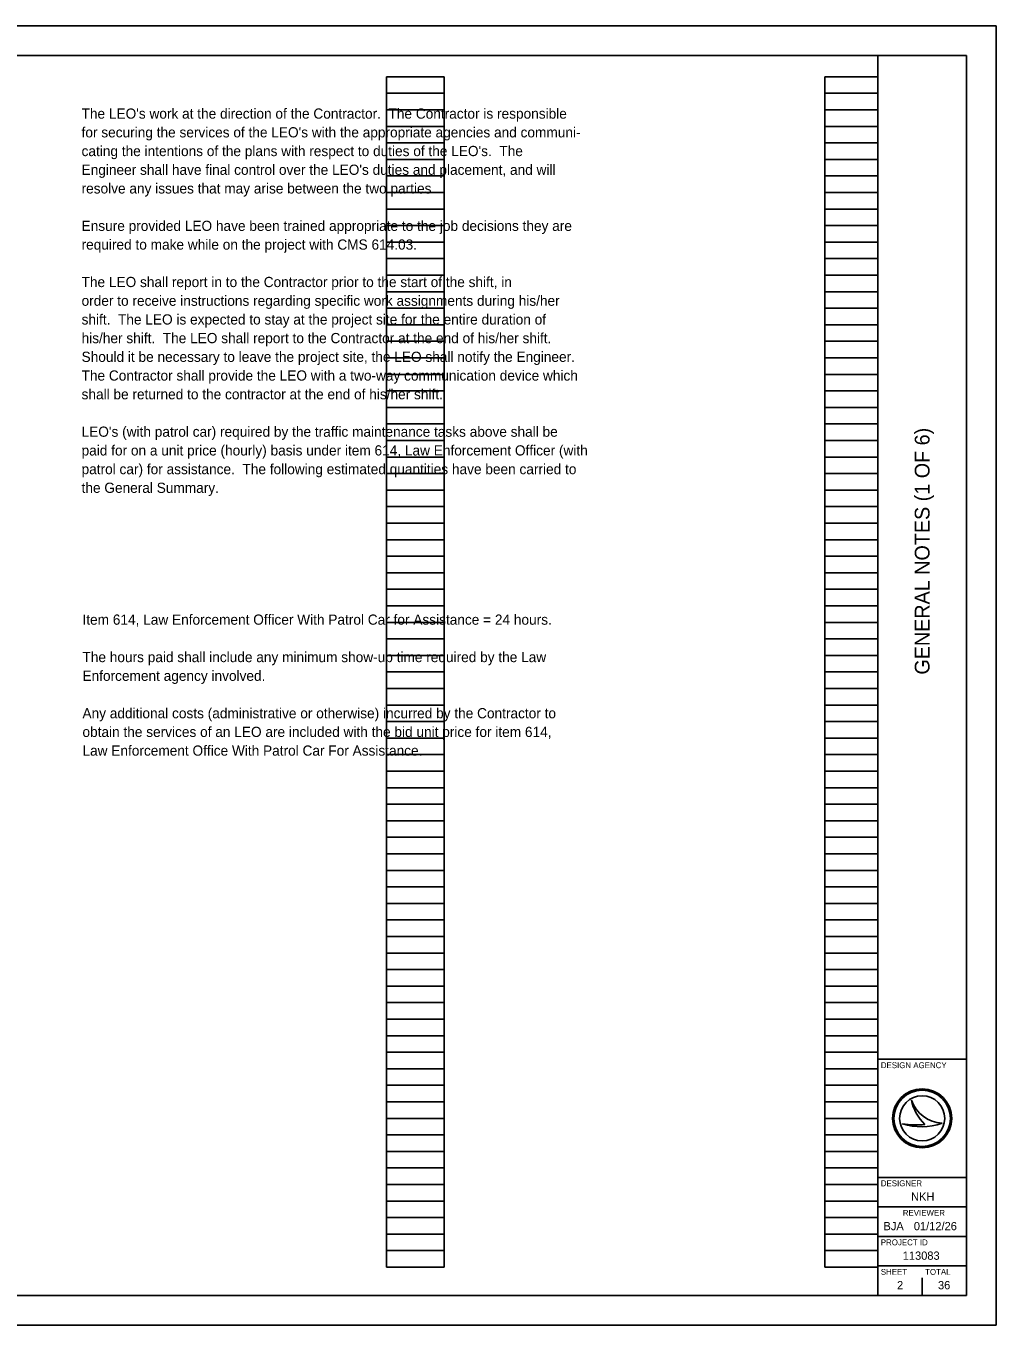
# Model space of a CAD drawing. Extents: x 0 to 34, y 0 to 22.
# Drawn here: x 17.58 to 34, y 0 to 22 of the extents above; entities that cross this region are included whole.
import ezdxf

# ---------------------------------------------------------------- set-up
doc = ezdxf.new("R2010")
doc.units = 0
for name, color, linetype in [('SH_Border', 7, 'Continuous'), ('SH_Cut_Line', 7, 'Continuous'), ('SH_Data', 7, 'Continuous'), ('SH_Text', 7, 'Continuous')]:
    doc.layers.add(name, color=color, linetype=linetype)

msp = doc.modelspace()

# ---------------------------------------------------------------- linework, layer by layer
at = {"layer": 'SH_Border'}
for p, q in [((32, 0.5), (32, 21.5)), ((32, 4.5), (33.5, 4.5)), ((32, 2.5), (33.5, 2.5)), ((32, 2), (33.5, 2)), ((32, 1.5), (33.5, 1.5)), ((32, 1), (33.5, 1))]:
    msp.add_line(p, q, dxfattribs=at)
msp.add_lwpolyline([(1.5, 21.5), (33.5, 21.5), (33.5, 0.5), (1.5, 0.5)], close=True, dxfattribs=at)
at = {"layer": 'SH_Cut_Line'}
msp.add_lwpolyline([(0, 0), (34, 0), (34, 22), (0, 22)], close=True, dxfattribs=at)
at = {"layer": 'SH_Data'}
for p, q in [((23.68, 0.98), (23.68, 21.14)), ((23.68, 21.14), (24.66, 21.14)), ((24.66, 0.98), (24.66, 21.14)), ((31.1, 0.98), (31.1, 21.14)), ((31.1, 21.14), (32, 21.14)), ((32, 0.98), (32, 21.14)), ((23.68, 20.86), (24.66, 20.86)), ((31.1, 20.86), (32, 20.86)), ((23.68, 20.58), (24.66, 20.58)), ((31.1, 20.58), (32, 20.58)), ((23.68, 20.3), (24.66, 20.3)), ((31.1, 20.3), (32, 20.3)), ((23.68, 20.02), (24.66, 20.02)), ((31.1, 20.02), (32, 20.02)), ((23.68, 19.74), (24.66, 19.74)), ((31.1, 19.74), (32, 19.74)), ((23.68, 19.46), (24.66, 19.46)), ((31.1, 19.46), (32, 19.46)), ((23.68, 19.18), (24.66, 19.18)), ((31.1, 19.18), (32, 19.18)), ((23.68, 18.9), (24.66, 18.9)), ((31.1, 18.9), (32, 18.9)), ((23.68, 18.62), (24.66, 18.62)), ((31.1, 18.62), (32, 18.62)), ((23.68, 18.34), (24.66, 18.34)), ((31.1, 18.34), (32, 18.34)), ((23.68, 18.06), (24.66, 18.06)), ((31.1, 18.06), (32, 18.06)), ((23.68, 17.78), (24.66, 17.78)), ((31.1, 17.78), (32, 17.78)), ((23.68, 17.5), (24.66, 17.5)), ((31.1, 17.5), (32, 17.5)), ((23.68, 17.22), (24.66, 17.22)), ((31.1, 17.22), (32, 17.22)), ((23.68, 16.94), (24.66, 16.94)), ((31.1, 16.94), (32, 16.94)), ((23.68, 16.66), (24.66, 16.66)), ((31.1, 16.66), (32, 16.66)), ((23.68, 16.38), (24.66, 16.38)), ((31.1, 16.38), (32, 16.38)), ((23.68, 16.1), (24.66, 16.1)), ((31.1, 16.1), (32, 16.1)), ((23.68, 15.82), (24.66, 15.82)), ((31.1, 15.82), (32, 15.82)), ((23.68, 15.54), (24.66, 15.54)), ((31.1, 15.54), (32, 15.54)), ((23.68, 15.26), (24.66, 15.26)), ((31.1, 15.26), (32, 15.26)), ((23.68, 14.98), (24.66, 14.98)), ((31.1, 14.98), (32, 14.98)), ((23.68, 14.7), (24.66, 14.7)), ((31.1, 14.7), (32, 14.7)), ((23.68, 14.42), (24.66, 14.42)), ((31.1, 14.42), (32, 14.42)), ((23.68, 14.14), (24.66, 14.14)), ((31.1, 14.14), (32, 14.14)), ((23.68, 13.86), (24.66, 13.86)), ((31.1, 13.86), (32, 13.86)), ((23.68, 13.58), (24.66, 13.58)), ((31.1, 13.58), (32, 13.58)), ((23.68, 13.3), (24.66, 13.3)), ((31.1, 13.3), (32, 13.3)), ((23.68, 13.02), (24.66, 13.02)), ((31.1, 13.02), (32, 13.02)), ((23.68, 12.74), (24.66, 12.74)), ((31.1, 12.74), (32, 12.74)), ((23.68, 12.46), (24.66, 12.46)), ((31.1, 12.46), (32, 12.46)), ((23.68, 12.18), (24.66, 12.18)), ((31.1, 12.18), (32, 12.18)), ((23.68, 11.9), (24.66, 11.9)), ((31.1, 11.9), (32, 11.9)), ((23.68, 11.62), (24.66, 11.62)), ((31.1, 11.62), (32, 11.62)), ((23.68, 11.34), (24.66, 11.34)), ((31.1, 11.34), (32, 11.34)), ((23.68, 11.06), (24.66, 11.06)), ((31.1, 11.06), (32, 11.06)), ((23.68, 10.78), (24.66, 10.78)), ((31.1, 10.78), (32, 10.78)), ((23.68, 10.5), (24.66, 10.5)), ((31.1, 10.5), (32, 10.5)), ((23.68, 10.22), (24.66, 10.22)), ((31.1, 10.22), (32, 10.22)), ((23.68, 9.94), (24.66, 9.94)), ((31.1, 9.94), (32, 9.94)), ((23.68, 9.66), (24.66, 9.66)), ((31.1, 9.66), (32, 9.66)), ((23.68, 9.38), (24.66, 9.38)), ((31.1, 9.38), (32, 9.38)), ((23.68, 9.1), (24.66, 9.1)), ((31.1, 9.1), (32, 9.1)), ((23.68, 8.82), (24.66, 8.82)), ((31.1, 8.82), (32, 8.82)), ((23.68, 8.54), (24.66, 8.54)), ((31.1, 8.54), (32, 8.54)), ((23.68, 8.26), (24.66, 8.26)), ((31.1, 8.26), (32, 8.26)), ((23.68, 7.98), (24.66, 7.98)), ((31.1, 7.98), (32, 7.98)), ((23.68, 7.7), (24.66, 7.7)), ((31.1, 7.7), (32, 7.7)), ((23.68, 7.42), (24.66, 7.42)), ((31.1, 7.42), (32, 7.42)), ((23.68, 7.14), (24.66, 7.14)), ((31.1, 7.14), (32, 7.14)), ((23.68, 6.86), (24.66, 6.86)), ((31.1, 6.86), (32, 6.86)), ((23.68, 6.58), (24.66, 6.58)), ((31.1, 6.58), (32, 6.58)), ((23.68, 6.3), (24.66, 6.3)), ((31.1, 6.3), (32, 6.3)), ((23.68, 6.02), (24.66, 6.02)), ((31.1, 6.02), (32, 6.02)), ((23.68, 5.74), (24.66, 5.74)), ((31.1, 5.74), (32, 5.74)), ((23.68, 5.46), (24.66, 5.46)), ((31.1, 5.46), (32, 5.46)), ((23.68, 5.18), (24.66, 5.18)), ((31.1, 5.18), (32, 5.18)), ((23.68, 4.9), (24.66, 4.9)), ((31.1, 4.9), (32, 4.9)), ((23.68, 4.62), (24.66, 4.62)), ((31.1, 4.62), (32, 4.62)), ((23.68, 4.34), (24.66, 4.34)), ((31.1, 4.34), (32, 4.34)), ((23.68, 4.06), (24.66, 4.06)), ((31.1, 4.06), (32, 4.06)), ((23.68, 3.78), (24.66, 3.78)), ((31.1, 3.78), (32, 3.78)), ((32.567, 3.81), (32.567, 3.81)), ((23.68, 3.5), (24.66, 3.5)), ((31.1, 3.5), (32, 3.5)), ((32.417, 3.41), (32.417, 3.41)), ((32.75, 3.5), (32.75, 3.5)), ((33.087, 3.419), (33.087, 3.419)), ((23.68, 3.22), (24.66, 3.22)), ((31.1, 3.22), (32, 3.22)), ((23.68, 2.94), (24.66, 2.94)), ((31.1, 2.94), (32, 2.94)), ((23.68, 2.66), (24.66, 2.66)), ((31.1, 2.66), (32, 2.66)), ((23.68, 2.38), (24.66, 2.38)), ((31.1, 2.38), (32, 2.38)), ((23.68, 2.1), (24.66, 2.1)), ((31.1, 2.1), (32, 2.1)), ((23.68, 1.82), (24.66, 1.82)), ((31.1, 1.82), (32, 1.82)), ((23.68, 1.54), (24.66, 1.54)), ((31.1, 1.54), (32, 1.54)), ((23.68, 1.26), (24.66, 1.26)), ((31.1, 1.26), (32, 1.26)), ((23.68, 0.98), (24.66, 0.98)), ((31.1, 0.98), (32, 0.98)), ((32.375, 0.675), (32.375, 0.675)), ((32.75, 0.5), (32.75, 0.8))]:
    msp.add_line(p, q, dxfattribs=at)
for radius in [0.5, 0.477, 0.477, 0.382]:
    msp.add_circle((32.75, 3.5), radius, dxfattribs=at)
for centre, radius, start, end in [((33.116, 3.998), 0.58, 198.9257, 198.9319), ((33.347, 3.97), 0.796, 191.6379, 191.6421), ((33.116, 3.998), 0.58, 198.9319, 267.1657), ((33.347, 3.97), 0.796, 191.6421, 226.0947), ((32.739, 4.37), 1.013, 251.4576, 290.0832), ((32.648, 4.654), 1.266, 259.4964, 259.4995), ((32.739, 4.37), 1.013, 251.4527, 251.4576), ((32.648, 4.654), 1.266, 259.4995, 276.6672)]:
    msp.add_arc(centre, radius, start, end, dxfattribs=at)

# ---------------------------------------------------------------- texts
msp.add_text('GENERAL NOTES (1 OF 6)', height=0.25, rotation=90, dxfattribs=at).set_placement((32.875, 11.015))
for s, height, p in [('DESIGN AGENCY', 0.1, (32.05, 4.35)), ('DESIGNER', 0.1, (32.05, 2.35)), ('NKH', 0.14, (32.562, 2.105)), ('REVIEWER', 0.1, (32.422, 1.85)), ('BJA', 0.14, (32.095, 1.605)), ('01/12/26', 0.14, (32.609, 1.605)), ('PROJECT ID', 0.1, (32.05, 1.35)), ('113083', 0.14, (32.421, 1.105)), ('SHEET', 0.1, (32.05, 0.85)), ('TOTAL', 0.1, (32.8, 0.85)), ('2', 0.14, (32.325, 0.605)), ('36', 0.14, (33.018, 0.605))]:
    msp.add_text(s, height=height, dxfattribs=at).set_placement(p)
at = {"layer": 'SH_Text'}
for s, p in [("The LEO's work at the direction of the Contractor.  The Contractor is responsible", (18.521, 20.43)), ("for securing the services of the LEO's with the appropriate agencies and communi-", (18.521, 20.113)), ("cating the intentions of the plans with respect to duties of the LEO's.  The ", (18.521, 19.796)), ("Engineer shall have final control over the LEO's duties and placement, and will ", (18.521, 19.479)), ('resolve any issues that may arise between the two parties.', (18.521, 19.163)), ('Ensure provided LEO have been trained appropriate to the job decisions they are', (18.521, 18.529)), ('required to make while on the project with CMS 614.03.', (18.521, 18.212)), ('The LEO shall report in to the Contractor prior to the start of the shift, in ', (18.521, 17.578)), ('order to receive instructions regarding specific work assignments during his/her ', (18.521, 17.261)), ('shift.  The LEO is expected to stay at the project site for the entire duration of ', (18.521, 16.944)), ('his/her shift.  The LEO shall report to the Contractor at the end of his/her shift.  ', (18.521, 16.628)), ('Should it be necessary to leave the project site, the LEO shall notify the Engineer.  ', (18.521, 16.311)), ('The Contractor shall provide the LEO with a two-way communication device which ', (18.521, 15.994)), ('shall be returned to the contractor at the end of his/her shift.', (18.521, 15.677)), ("LEO's (with patrol car) required by the traffic maintenance tasks above shall be ", (18.521, 15.043)), ('paid for on a unit price (hourly) basis under item 614, Law Enforcement Officer (with ', (18.521, 14.726)), ('patrol car) for assistance.  The following estimated quantities have been carried to ', (18.521, 14.409)), ('the General Summary.', (18.521, 14.093)), ('Item 614, Law Enforcement Officer With Patrol Car for Assistance = 24 hours.', (18.536, 11.86)), ('The hours paid shall include any minimum show-up time required by the Law ', (18.536, 11.226)), ('Enforcement agency involved.', (18.536, 10.909)), ('Any additional costs (administrative or otherwise) incurred by the Contractor to ', (18.536, 10.275)), ('obtain the services of an LEO are included with the bid unit price for item 614,', (18.536, 9.959)), ('Law Enforcement Office With Patrol Car For Assistance.', (18.536, 9.642))]:
    msp.add_text(s, height=0.17284, dxfattribs=at).set_placement(p)

doc.saveas('drawing.dxf')
